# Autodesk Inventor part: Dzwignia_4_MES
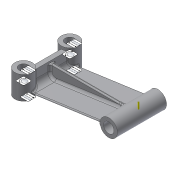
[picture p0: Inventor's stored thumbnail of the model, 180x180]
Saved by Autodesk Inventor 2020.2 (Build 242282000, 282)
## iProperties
Created: 2011-11
Part Number: Dzwignia_4_MES
Material: Aluminium-6061
Document SubType Name: Modeling
Designer: F.Stasiak
Density: 2.71 g/cm^3
Mass: 462.108 g
Surface Area: 631.896 cm^2
Volume: 170.52 cm^3
Appearance: Aluminium — płaski
Catalog Web Link: www.expertbooks.pl
Manager: www.cadconsulting.pl
Company: Fabian Stasiak CAD Consulting
Author: F.Stasiak
Subject: Zbiór ćwiczeń. Autodesk Inventor 2020. Kurs Professional
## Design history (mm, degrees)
sketch "Sketch2"
  geometry: L1 (0, 0)-(0, 30); L2 (0, 30)-(-150, 8.919); L3 (-150, 8.919)-(-150, 0); L4 (-150, 0)-(0, 0)
  constraints: 8 end point, 1 parallel, 1 perpendicular, 1 vertical
  dimensions: "d0" = 30 distance of L1.start L1.end; "d1" = 150 distance of L3.end L1.start; "d2" = 8 deg angle of L2 L4
extrude "Extrusion1" new body sketch "Sketch2" stored distance "d3" = 80; taper "d4" = 0 deg
shell "Shell1" dims "d6" = 3, "d7" = 8
fillet "Fillet1" dims "d8" = 10
sketch "Sketch3"
  geometry: L1 (-150, 0)-(-150, 8.919) reference; C1 r 15 at (-150, 8.919); 1 further point
  constraints: 1 centre point, 1 coincident
  dimensions: "d9" = 30 diameter of C1
extrude "Extrusion2" join sketch "Sketch3" stored distance "d10" = 85; taper "d11" = 0 deg
fillet "Zaokrąglenie10" dims "d66" = 1.5
fillet "Fillet3" dims "d41" = 5
sketch "Sketch7"
  geometry: L1 (-150, 23.919)-(-43.269, 23.919); L2 (0, 0)-(0, 28.485) reference; L3 (0, 3)-(-136.217, 3); L4 (-6.5, 0)-(0, 0) reference; A1 r 15 centre (-150, 8.919) between (-150, 23.919) and (-136.217, 3) reference
  constraints: 4 end point, 2 point on circle, 1 parallel, 1 perpendicular, 1 point on line, 1 tangent
  dimensions: "d56" = 3 distance between parallel lines of L3 L4
feature "Żebro3" dims "d57" = 1, "d58" = 5, "d59" = 0, "d60" = 0, "d61" = 1, "d62" = 1
fillet "Zaokrąglenie8" dims "d63" = 2, "d64" = 4
pattern_linear "Rectangular Pattern1" dims "d39" = 15
sketch "Sketch4"
  geometry: C1 r 15 at (0, 0) reference; C2 r 9 at (0, 0); 1 further point
  constraints: 1 centre point, 1 coincident
  dimensions: "d12" = 18 diameter of C2
extrude "Extrusion3" cut sketch "Sketch4" extent not by distance; stored distance "d13" = 80; taper "d14" = 0 deg
sketch "Sketch8"
  geometry: C1 r 15 at (0, 40); C2 r 15 at (0, -40); 2 further points
  constraints: 2 centre point, 1 coincident
  dimensions: "d45" = 30 diameter of C1; "d46" = 30 diameter of C2
extrude "Extrusion6" join sketch "Sketch8" distance "d47" = 35; taper "d49" = 0 deg; dims "d48" = 5, "d50" = 0
sketch "Sketch9"
  geometry: C1 r 15 at (0, 0) reference; C2 r 8 at (0, 0); C3 r 15 at (0, 80) reference; C4 r 8 at (0, 80); 1 further point
  constraints: 2 centre point, 2 coincident
  dimensions: "d51" = 16 diameter of C2; "d52" = 16 diameter of C4
extrude "Extrusion7" cut sketch "Sketch9" extent not by distance; stored distance "d53" = 35; taper "d54" = 0 deg
fillet "Fillet7" dims "d55" = 3
body "Solid1"
node "Projected Loop2"
other parameters: "sa_0" = 0, "sa_1" = 0, "sa_2" = 600000
